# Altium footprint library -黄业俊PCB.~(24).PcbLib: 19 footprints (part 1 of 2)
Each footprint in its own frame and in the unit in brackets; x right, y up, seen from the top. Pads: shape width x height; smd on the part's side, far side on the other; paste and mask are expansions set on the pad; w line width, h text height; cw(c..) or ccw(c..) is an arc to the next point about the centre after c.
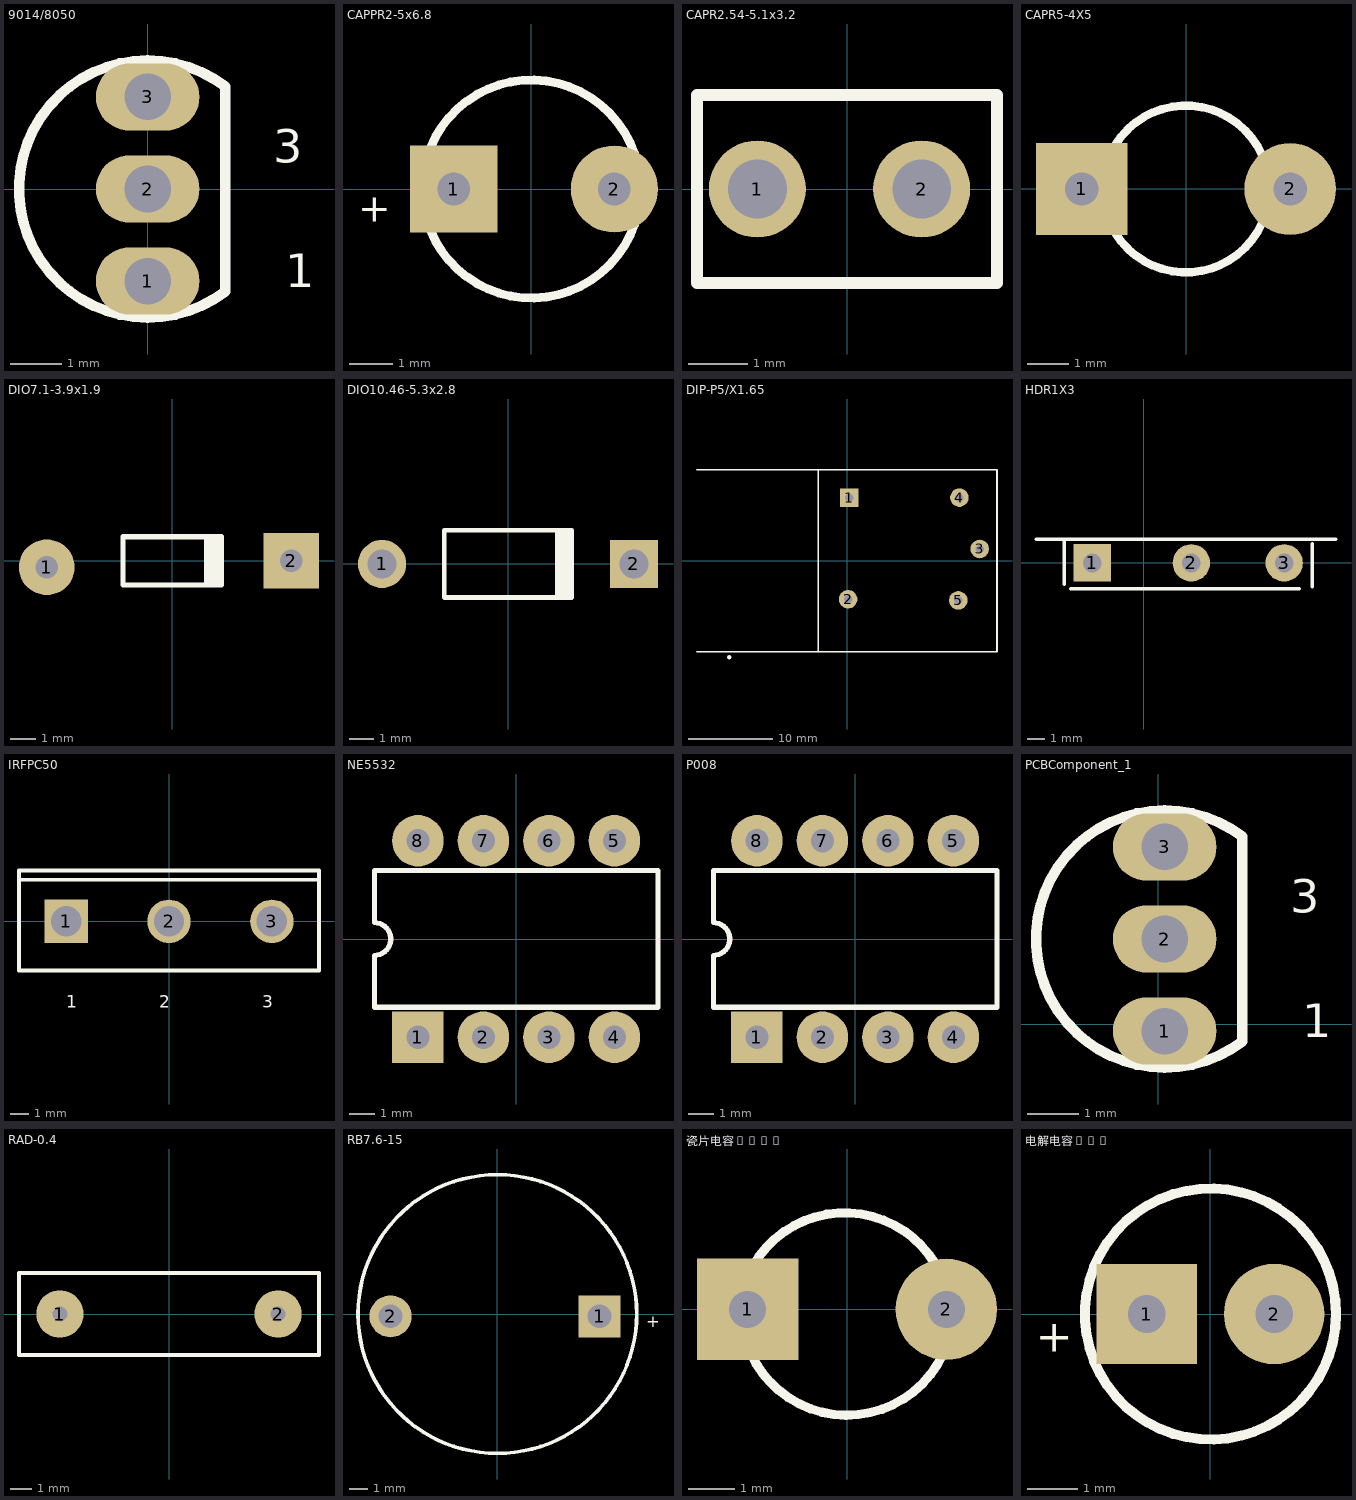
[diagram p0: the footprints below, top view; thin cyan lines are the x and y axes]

## 9014/8050 [mm]
pads (3):
  oval 2x1.3 hole 0.9: 1(0,-1.778) 2(0,0) 3(0,1.778)
Top Overlay:
  lines w0.2: 1.5,-1.98 cw(c0,0) 1.5,1.98 1.5,-1.98
  text "3" at 2.43,0.51 h0.65
  text "1" at 2.66,-1.9 h0.65

## CAPPR2-5x6.8 [mm]
pads (2):
  rect 2x2 hole 0.75: 1(-1.778,0)
  round 2 hole 0.75: 2(1.905,0)
Top Overlay:
  circle w0.2: c0,0 r2.5
  text "+" at -3.975,-0.75 h0.65

## CAPR2.54-5.1x3.2 [mm]
pads (2):
  round 1.65 hole 1: 1(-1.524,0) 2(1.27,0)
Top Overlay:
  lines w0.2: -2.55,-1.6 2.55,-1.6 2.55,1.6 -2.55,1.6 -2.55,-1.6

## CAPR5-4X5 [mm]
pads (2):
  rect 2.2x2.2 hole 0.8: 1(-2.5,0)
  round 2.2 hole 0.8: 2(2.5,0)
Top Overlay:
  lines w0.2: -1.687,-1.075 ccw(c0,0) 1.819,-0.832 ; -1.687,1.075 cw(c0,0) 1.819,0.832

## DIO7.1-3.9x1.9 [mm]
pads (2):
  round 2.2 hole 0.9: 1(-4.953,-0.254)
  rect 2.2x2.2 hole 0.9: 2(4.699,0)
Top Overlay:
  rectangle: 1.25,-0.95 2.05,0.95
  lines w0.2: 1.95,-0.95 -1.95,-0.95 -1.95,0.95 1.95,0.95

## DIO10.46-5.3x2.8 [mm]
pads (2):
  round 2 hole 1.2: 1(-5.23,0)
  rect 2x2 hole 1.2: 2(5.23,0)
Top Overlay:
  rectangle: 1.95,-1.404 2.75,1.396
  lines w0.2: 2.65,-1.4 -2.65,-1.4 -2.65,1.4 2.65,1.4

## DIP-P5/X1.65 [mm]
pads (5):
  rect 2.2x2.2 hole 1: 1(0.254,7.493)
  round 2.2 hole 1: 2(0.127,-4.572) 3(15.748,1.397) 4(13.335,7.493) 5(13.208,-4.699)
Top Overlay:
  circle w0.25: c-13.97,-11.45 r0.125
  lines w0.2: -17.8,-10.8 17.8,-10.8 17.8,10.8 -17.8,10.8 ; -3.429,-10.795 -3.429,10.805

## HDR1X3 [mm]
pads (3):
  rect 2.2x2.2 hole 1.1: 1(-3.048,0)
  round 2.2 hole 1.1: 2(2.794,0) 3(8.255,0)
Top Overlay:
  lines w0.2: -6.35,1.397 11.303,1.397 ; -4.699,-1.27 -4.699,1.27 ; -4.318,-1.524 9.144,-1.524 ; 9.906,-1.397 9.906,1.143

## IRFPC50 [mm]
pads (3):
  rect 2.3x2.3 hole 1.6: 1(-5.45,0)
  round 2.3 hole 1.6: 2(0,0) 3(5.45,0)
Top Overlay:
  lines w0.2: -7.95,2.2 7.95,2.2 ; -7.95,-2.6 7.95,-2.6 7.95,2.7 -7.95,2.7 -7.95,-2.6
  text "1" at -5.45,-4.575 h0.65
  text "2" at -0.508,-4.575 h0.65
  text "3" at 4.942,-4.575 h0.65

## NE5532 [mm]
pads (8):
  rect 2x2 hole 0.9: 1(-3.81,-3.81)
  round 2 hole 0.9: 2(-1.27,-3.81) 3(1.27,-3.81) 4(3.81,-3.81) 5(3.81,3.81) 6(1.27,3.81) 7(-1.27,3.81) 8(-3.81,3.81)
Top Overlay:
  lines w0.2: -5.5,-2.65 -5.5,-0.635 ccw(c-5.5,0) -5.5,0.635 -5.5,2.65 5.5,2.65 5.5,-2.65 -5.5,-2.65

## P008 [mm]
pads (8):
  rect 2x2 hole 0.9: 1(-3.81,-3.81)
  round 2 hole 0.9: 2(-1.27,-3.81) 3(1.27,-3.81) 4(3.81,-3.81) 5(3.81,3.81) 6(1.27,3.81) 7(-1.27,3.81) 8(-3.81,3.81)
Top Overlay:
  lines w0.2: -5.5,-2.65 5.5,-2.65 5.5,2.65 -5.5,2.65 -5.5,0.635 cw(c-5.5,0) -5.5,-0.635 -5.5,-2.65

## PCBComponent_1 [mm]
pads (3):
  oval 2x1.3 hole 0.9: 1(0.127,-0.127) 2(0.127,1.651) 3(0.127,3.429)
Top Overlay:
  lines w0.2: 1.627,-0.329 cw(c0.127,1.651) 1.627,3.631 1.627,-0.329
  text "1" at 2.787,-0.249 h0.65
  text "3" at 2.557,2.161 h0.65

## RAD-0.4 [mm]
pads (2):
  round 2.2 hole 0.7: 1(-5.08,0) 2(5.08,0)
Top Overlay:
  lines w0.2: -6.985,-1.905 6.985,-1.905 6.985,1.905 -6.985,1.905 -6.985,-1.905

## RB7.6-15 [mm]
pads (2):
  rect 2.3x2.3 hole 1.3: 1(5.588,-0.127)
  round 2.3 hole 1.3: 2(-5.842,-0.127)
Top Overlay:
  circle w0.2: c0,0 r7.62
  text "+" at 8.132,-0.737 h0.65

## 瓷片电容C104 [mm]
pads (2):
  rect 2.2x2.2 hole 0.8: 1(-2.159,0)
  round 2.2 hole 0.8: 2(2.159,0)
Top Overlay:
  lines w0.2: -2.107,-0.922 ccw(c0,0) 2.092,-0.956 ; -2.043,0.949 cw(c-0.051,-0.201) 2.041,0.756

## 电解电容1uf [mm]
pads (2):
  rect 2x2 hole 0.75: 1(-1.27,0)
  round 2 hole 0.75: 2(1.27,0)
Top Overlay:
  circle w0.2: c0,0 r2.5
  text "+" at -3.475,-0.75 h0.65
